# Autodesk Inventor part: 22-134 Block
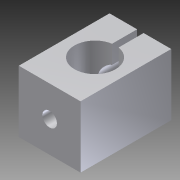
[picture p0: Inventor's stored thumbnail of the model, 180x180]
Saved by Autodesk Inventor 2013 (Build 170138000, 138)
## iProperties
Created: 2004-11
Part Number: 22-134 Block
Document SubType Name: Modeling
Designer: Autodesk, Inc.
Manufacturer: Standard
Standards Organization: Custom
Description: SLIDE COLLAR BLOCK
Mass: 55.6675 g
Surface Area: 149.466 cm^2
Volume: 55.6675 cm^3
Density: 1 g/cm^3
Material: Allgemein
CAGE: 1LJX3
Dept. ID: Product Design
Description #2: ---
Finish #1: ---
Finish #2: ---
Material ID: ---
Project Number: ---
Author: Autodesk, Inc.
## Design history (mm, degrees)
sketch "Sketch1"
  geometry: L1 (-19.05, 19.05)-(19.05, 19.05); L2 (19.05, 19.05)-(19.05, -19.05); L3 (19.05, -19.05)-(-19.05, -19.05); L4 (-19.05, -19.05)-(-19.05, 19.05); 3 further points
  constraints: 8 end point, 2 midpoint, 2 parallel, 2 perpendicular, 1 horizontal, 1 horizontal alignment, 1 vertical alignment
  dimensions: "d0" = 38.1 distance of L1.start L1.end
extrude "Extrusion1" new body sketch "Sketch1" distance "d1" = 56; taper "d2" = 0 deg
sketch "Sketch2"
  geometry: L1 (0, 0)-(38.1, 0) reference; L2 (0, -56)-(38.1, -56) reference; L3 (17.05, 0)-(21.05, 0); L4 (21.05, 0)-(21.05, -28); L5 (21.05, -28)-(17.05, -28); L6 (17.05, -28)-(17.05, 0); C1 r 12.7 at (19.05, -28); 2 further points
  constraints: 8 end point, 3 midpoint, 2 parallel, 1 centre point, 1 coincident, 1 horizontal, 1 perpendicular, 1 point on line, 1 vertical alignment
  dimensions: "d3" = 28 distance from line of C1.centre L2; "d4" = 25.4 diameter of C1; "d5" = 4 distance between parallel lines of L4 L6
extrude "Extrusion2" cut sketch "Sketch2" stored distance "d6" = 56; taper "d7" = 0 deg
workplane "Work Plane1"
sketch "Sketch3"
  geometry: 1 further point
hole "Hole1" sketch "Sketch3" diameter "d9" = 9; stored, may be unused: countersink angle "d13" = 90 deg, drill point angle "d15" = 118 deg; dims "d10" = 6, "d11" = 17.3, "d12" = 2, "d14" = 8
sketch "Sketch4"
  geometry: C1 r 8 at (0, 0); 1 further point
  constraints: 1 centre point, 1 coincident
  dimensions: "d16" = 16 diameter of C1
extrude "Extrusion3" cut sketch "Sketch4" stored distance "d17" = 56; taper "d18" = 0 deg
sketch "Sketch5"
  geometry: L1 (0, 0)-(0, 38.1) reference; L2 (4.905, 27.643)-(6.56, 27.643); L3 (6.56, 27.643)-(6.56, 10.457); L4 (6.56, 10.457)-(4.905, 10.457); L5 (4.905, 10.457)-(4.905, 27.643); C1 r 3.823 at (5.712, 19.05); 2 further points
  constraints: 8 end point, 2 horizontal alignment, 2 midpoint, 2 parallel, 1 centre point, 1 horizontal, 1 perpendicular
extrude "Extrusion4" join sketch "Sketch5" distance "d19" = 6; taper "d20" = 0 deg
body "Solid1"
other parameters: "d8" = -8
